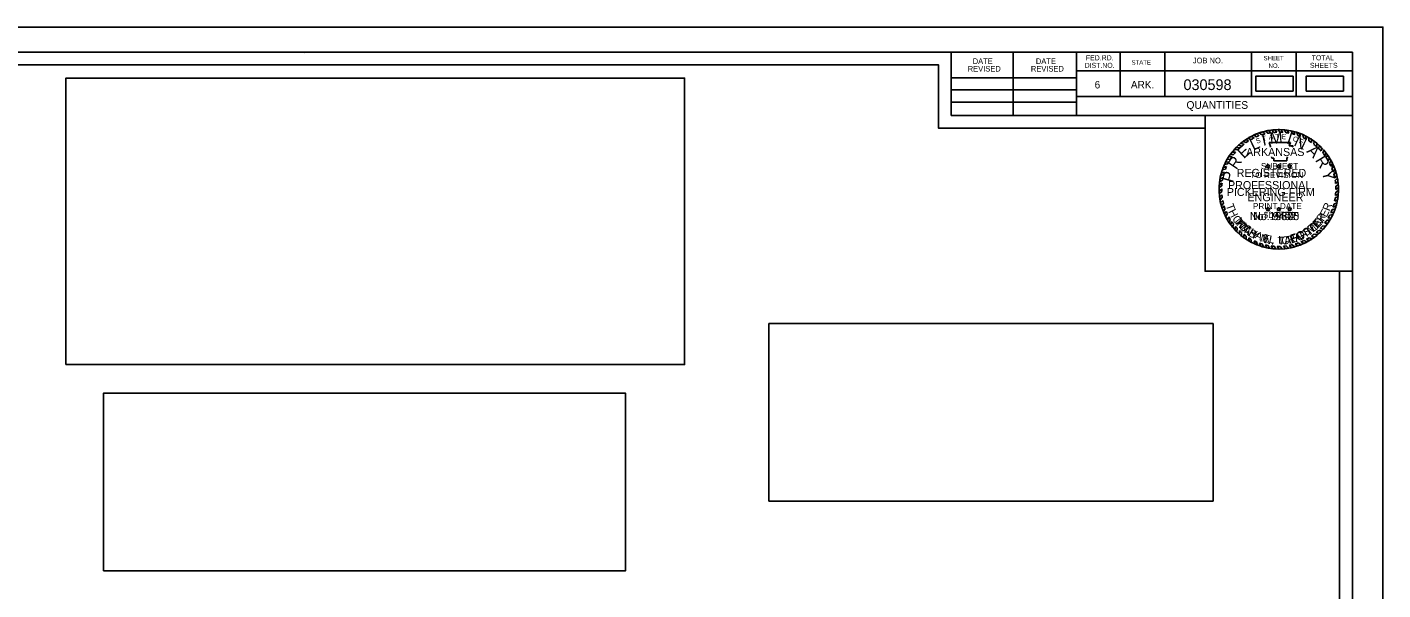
# Model space of a CAD drawing. Extents: x 1369904 to 1372237, y 380119 to 380332.
# Drawn here: x 1370525.1 to 1370736.9, y 380244.5 to 380332.4 of the extents above; entities that cross this region are included whole.
import ezdxf

# ---------------------------------------------------------------- set-up
doc = ezdxf.new("R2010")
doc.units = 0
for name, color, linetype in [('Default', 7, 'Continuous'), ('R_Border', 7, 'Continuous'), ('R_Border Notes', 7, 'Continuous'), ('R_No Plot', 7, 'Continuous'), ('STAMP_PE_CRAFTON', 7, 'Continuous'), ('STAMP_PE_FOSTER', 7, 'Continuous'), ('STAMP_PE_SEAL-INFO', 7, 'Continuous'), ('STAMP_PE_TAEGTMEYER', 7, 'Continuous'), ('STAMP_PE_TXT', 7, 'Continuous'), ('STAMP_PRELIMINARY', 7, 'Continuous')]:
    doc.layers.add(name, color=color, linetype=linetype)

msp = doc.modelspace()

# ---------------------------------------------------------------- linework, layer by layer
at = {"layer": 'Default'}
for points in [[(1370531.17, 380279.71), (1370627.79, 380279.71), (1370627.79, 380324.44), (1370531.17, 380324.44)], [(1370717, 380322.41), (1370722.83, 380322.41), (1370722.83, 380324.72), (1370717, 380324.72)], [(1370724.87, 380322.41), (1370730.7, 380322.41), (1370730.7, 380324.72), (1370724.87, 380324.72)], [(1370640.96, 380258.39), (1370710.35, 380258.39), (1370710.35, 380286.11), (1370640.96, 380286.11)], [(1370537.03, 380247.51), (1370618.58, 380247.51), (1370618.58, 380275.22), (1370537.03, 380275.22)]]:
    msp.add_lwpolyline(points, close=True, dxfattribs=at)
at = {"layer": 'R_Border'}
for p, q in [((1370415.92, 380328.5), (1370732.1, 380328.5)), ((1370568.44, 380328.24), (1370568.44, 380328.24)), ((1370568.44, 380328.24), (1370568.44, 380328.24)), ((1370669.46, 380318.62), (1370669.46, 380328.5)), ((1370679.14, 380318.62), (1370679.14, 380328.5)), ((1370689, 380328.5), (1370689, 380318.62)), ((1370695.84, 380328.5), (1370695.84, 380321.56)), ((1370702.78, 380328.5), (1370702.78, 380321.56)), ((1370716.36, 380328.5), (1370716.36, 380321.56)), ((1370723.3, 380328.5), (1370723.3, 380321.56)), ((1370732.1, 380123.04), (1370732.1, 380328.5)), ((1370669.46, 380324.48), (1370689, 380324.48)), ((1370732.1, 380325.56), (1370689, 380325.56)), ((1370732.1, 380325.58), (1370732.1, 380325.58)), ((1370669.46, 380322.62), (1370689, 380322.62)), ((1370669.46, 380320.68), (1370689, 380320.68)), ((1370732.1, 380321.56), (1370689, 380321.56)), ((1370691.96, 380321.56), (1370732.1, 380321.56)), ((1370732.1, 380318.62), (1370669.46, 380318.62))]:
    msp.add_line(p, q, dxfattribs=at)
at = {"layer": 'R_No Plot'}
for points in [[(1370403.52, 380332.4), (1370736.86, 380332.4), (1370736.86, 380119.06), (1370403.52, 380119.06)], [(1370730.1, 380227.77), (1370417.92, 380227.77), (1370417.92, 380326.5), (1370667.46, 380326.5), (1370667.46, 380316.62), (1370685, 380316.62), (1370709.1, 380316.62), (1370709.1, 380294.29), (1370730.1, 380294.29)], [(1370417.92, 380326.5), (1370667.46, 380326.5), (1370667.46, 380316.62), (1370685, 380316.62), (1370709.1, 380316.62), (1370709.1, 380294.29), (1370730.1, 380294.29), (1370730.1, 380125.04), (1370417.92, 380125.04)], [(1370709.1, 380318.62), (1370732.1, 380318.62), (1370732.1, 380294.29), (1370709.1, 380294.29)]]:
    msp.add_lwpolyline(points, close=True, dxfattribs=at)
at = {"layer": 'STAMP_PE_SEAL-INFO'}
for p, q in [((1370716.71, 380315.54), (1370717.1, 380315.26)), ((1370717.22, 380315.75), (1370717.51, 380315.43)), ((1370717.56, 380315.88), (1370717.94, 380315.57)), ((1370718.16, 380316.06), (1370718.44, 380315.71)), ((1370718.54, 380316.16), (1370718.9, 380315.82)), ((1370719.03, 380316.26), (1370719.32, 380315.89)), ((1370719.54, 380316.33), (1370719.82, 380315.95)), ((1370720.28, 380315.97), (1370719.96, 380316.37)), ((1370720.77, 380315.98), (1370720.5, 380316.39)), ((1370721.23, 380315.96), (1370720.97, 380316.38)), ((1370721.74, 380315.91), (1370721.45, 380316.35)), ((1370722.16, 380315.84), (1370721.91, 380316.3)), ((1370722.73, 380315.72), (1370722.55, 380316.18)), ((1370723.13, 380315.62), (1370722.97, 380316.09)), ((1370723.58, 380315.47), (1370723.44, 380315.95)), ((1370724, 380315.31), (1370723.85, 380315.81)), ((1370724.46, 380315.1), (1370724.36, 380315.6)), ((1370713.97, 380313.61), (1370714.51, 380313.57)), ((1370714.3, 380313.94), (1370714.76, 380313.8)), ((1370714.65, 380314.24), (1370715.17, 380314.14)), ((1370715.02, 380314.56), (1370715.48, 380314.36)), ((1370715.44, 380314.83), (1370715.88, 380314.63)), ((1370715.83, 380315.07), (1370716.26, 380314.85)), ((1370716.28, 380315.33), (1370716.74, 380315.1)), ((1370719.08, 380314.36), (1370722.42, 380314.36)), ((1370719.2, 380314.05), (1370719.08, 380314.36)), ((1370719.3, 380313.75), (1370719.2, 380314.05)), ((1370719.31, 380313.64), (1370719.3, 380313.75)), ((1370722.42, 380314.36), (1370722.2, 380313.87)), ((1370722.2, 380313.87), (1370722.83, 380313.87)), ((1370722.83, 380313.87), (1370722.68, 380313.64)), ((1370724.9, 380314.87), (1370724.82, 380315.38)), ((1370725.29, 380314.65), (1370725.25, 380315.15)), ((1370725.73, 380314.36), (1370725.7, 380314.88)), ((1370726.09, 380314.1), (1370726.12, 380314.58)), ((1370726.53, 380313.72), (1370726.55, 380314.25)), ((1370726.85, 380313.43), (1370726.92, 380313.93)), ((1370727.21, 380313.06), (1370727.27, 380313.58)), ((1370712.31, 380311.32), (1370712.81, 380311.38)), ((1370712.54, 380311.74), (1370713.03, 380311.76)), ((1370712.79, 380312.14), (1370713.3, 380312.18)), ((1370713.02, 380312.49), (1370713.52, 380312.48)), ((1370713.3, 380312.86), (1370713.85, 380312.88)), ((1370713.64, 380313.27), (1370714.17, 380313.23)), ((1370719.5, 380311.93), (1370719.48, 380312.15)), ((1370719.82, 380311.93), (1370719.5, 380311.93)), ((1370719.82, 380311.5), (1370719.82, 380311.93)), ((1370721.85, 380311.5), (1370719.82, 380311.5)), ((1370721.86, 380311.84), (1370721.85, 380311.5)), ((1370721.94, 380312.15), (1370721.86, 380311.84)), ((1370727.48, 380312.74), (1370727.62, 380313.21)), ((1370727.8, 380312.32), (1370727.94, 380312.82)), ((1370728.02, 380312.01), (1370728.2, 380312.47)), ((1370728.33, 380311.51), (1370728.51, 380312)), ((1370728.53, 380311.14), (1370728.76, 380311.59)), ((1370711.52, 380309.18), (1370711.99, 380309.37)), ((1370711.63, 380309.59), (1370712.11, 380309.76)), ((1370711.79, 380310.09), (1370712.27, 380310.23)), ((1370711.94, 380310.5), (1370712.44, 380310.64)), ((1370712.12, 380310.93), (1370712.62, 380311.03)), ((1370728.76, 380310.66), (1370728.99, 380311.15)), ((1370728.9, 380310.32), (1370729.17, 380310.76)), ((1370729.1, 380309.77), (1370729.37, 380310.25)), ((1370729.2, 380309.41), (1370729.5, 380309.86)), ((1370729.34, 380308.85), (1370729.66, 380309.3)), ((1370711.71, 380307.62), (1370711.29, 380307.36)), ((1370711.69, 380307.12), (1370711.29, 380306.79)), ((1370711.74, 380308.04), (1370711.31, 380307.76)), ((1370711.8, 380308.48), (1370711.36, 380308.25)), ((1370711.89, 380308.94), (1370711.42, 380308.69)), ((1370729.41, 380308.47), (1370729.76, 380308.82)), ((1370729.47, 380307.96), (1370729.85, 380308.3)), ((1370729.51, 380307.54), (1370729.9, 380307.84)), ((1370729.52, 380307.03), (1370729.92, 380307.35)), ((1370711.7, 380306.72), (1370711.31, 380306.39)), ((1370711.73, 380306.22), (1370711.36, 380305.86)), ((1370711.78, 380305.79), (1370711.43, 380305.42)), ((1370711.86, 380305.33), (1370711.52, 380304.96)), ((1370729.22, 380304.77), (1370729.69, 380304.98)), ((1370729.33, 380305.23), (1370729.78, 380305.42)), ((1370729.42, 380305.73), (1370729.86, 380305.95)), ((1370729.47, 380306.11), (1370729.9, 380306.37)), ((1370729.51, 380306.62), (1370729.93, 380306.9)), ((1370711.96, 380304.91), (1370711.64, 380304.5)), ((1370712.08, 380304.47), (1370711.78, 380304.05)), ((1370712.22, 380304.04), (1370711.94, 380303.63)), ((1370712.39, 380303.62), (1370712.12, 380303.19)), ((1370712.56, 380303.23), (1370712.33, 380302.77)), ((1370728.56, 380303.05), (1370729.05, 380303.12)), ((1370728.72, 380303.39), (1370729.21, 380303.48)), ((1370728.94, 380303.9), (1370729.42, 380304.03)), ((1370729.07, 380304.28), (1370729.56, 380304.48)), ((1370712.79, 380302.77), (1370712.6, 380302.28)), ((1370713.03, 380302.37), (1370712.84, 380301.9)), ((1370713.23, 380302.06), (1370713.12, 380301.51)), ((1370713.51, 380301.67), (1370713.41, 380301.14)), ((1370713.82, 380301.29), (1370713.73, 380300.77)), ((1370714.12, 380300.95), (1370714.06, 380300.43)), ((1370727.09, 380300.95), (1370727.56, 380300.86)), ((1370727.47, 380301.38), (1370727.93, 380301.3)), ((1370727.78, 380301.78), (1370728.28, 380301.78)), ((1370728.12, 380302.27), (1370728.59, 380302.26)), ((1370728.29, 380302.55), (1370728.79, 380302.61)), ((1370714.44, 380300.63), (1370714.41, 380300.1)), ((1370714.79, 380300.32), (1370714.78, 380299.79)), ((1370715.15, 380300.02), (1370715.16, 380299.5)), ((1370715.48, 380299.77), (1370715.52, 380299.25)), ((1370715.91, 380299.49), (1370715.97, 380298.98)), ((1370716.26, 380299.28), (1370716.35, 380298.77)), ((1370716.74, 380299.03), (1370716.9, 380298.51)), ((1370717.11, 380298.87), (1370717.29, 380298.35)), ((1370717.61, 380298.67), (1370717.82, 380298.17)), ((1370723.65, 380298.69), (1370724.09, 380298.42)), ((1370724.07, 380298.85), (1370724.49, 380298.59)), ((1370724.53, 380299.06), (1370725.01, 380298.85)), ((1370724.94, 380299.28), (1370725.35, 380299.04)), ((1370725.35, 380299.52), (1370725.8, 380299.33)), ((1370725.69, 380299.75), (1370726.13, 380299.56)), ((1370726.16, 380300.09), (1370726.62, 380299.95)), ((1370726.43, 380300.32), (1370726.9, 380300.19)), ((1370726.83, 380300.69), (1370727.27, 380300.55)), ((1370718.02, 380298.54), (1370718.24, 380298.05)), ((1370718.52, 380298.4), (1370718.74, 380297.93)), ((1370718.92, 380298.31), (1370719.17, 380297.86)), ((1370719.42, 380298.23), (1370719.66, 380297.79)), ((1370719.86, 380298.19), (1370720.13, 380297.76)), ((1370720.34, 380298.16), (1370720.65, 380297.74)), ((1370720.8, 380298.16), (1370721.15, 380297.76)), ((1370721.32, 380298.18), (1370721.65, 380297.8)), ((1370721.76, 380298.23), (1370722.13, 380297.87)), ((1370722.21, 380298.3), (1370722.59, 380297.96)), ((1370722.7, 380298.4), (1370723.08, 380298.08)), ((1370723.16, 380298.53), (1370723.57, 380298.23))]:
    msp.add_line(p, q, dxfattribs=at)
for radius, start, end in [(9.32, 111.3124, 114.7026), (9.32, 105.2339, 109.0352), (8.91, 104.0352, 107.3615), (9.32, 99.7525, 102.7765), (8.91, 98.258, 101.0329), (9.32, 93.9381, 96.5517), (8.91, 92.1102, 95.0367), (9.32, 87.7298, 90.6707), (8.91, 85.9628, 88.9097), (9.32, 81.9732, 84.8236), (8.91, 79.9264, 82.696), (9.32, 75.3125, 77.9426), (8.91, 73.5575, 76.2314), (9.32, 69.6061, 72.3058), (9.32, 63.1329, 66.2704), (9.32, 135.4021, 138.3031), (8.91, 133.1331, 136.2562), (9.32, 129.7326, 132.5376), (8.91, 127.5297, 130.9683), (9.32, 123.6199, 126.5906), (8.91, 121.9746, 125.11), (9.32, 117.6544, 120.8099), (8.91, 115.6869, 119.1583), (8.91, 110.3086, 113.1659), (8.91, 67.6248, 70.504), (8.91, 61.1558, 64.3784), (9.32, 56.9003, 60.0942), (8.91, 54.9238, 58.2702), (8.91, 48.3016, 52.0395), (9.32, 50.3492, 53.7159), (8.91, 42.2212, 45.5512), (9.32, 44.3405, 47.3929), (9.32, 152.864, 155.5189), (9.32, 147.0072, 149.899), (8.91, 151.0315, 153.573), (9.32, 141.6056, 144.4486), (8.91, 145.0197, 148.2104), (8.91, 139.301, 142.5873), (8.91, 36.135, 39.5311), (9.32, 38.1247, 41.2316), (8.91, 29.9032, 33.6645), (9.32, 31.9614, 35.4294), (9.32, 25.9391, 29.0125), (9.32, 164.3068, 166.894), (9.32, 158.4077, 161.0701), (8.91, 162.4331, 165.0013), (8.91, 156.3402, 159.2319), (8.91, 23.7732, 27.2211), (8.91, 17.6802, 21.4251), (9.32, 19.9538, 23.3141), (8.91, 11.5444, 15.2364), (9.32, 13.8421, 17.4447), (9.32, 175.7409, 178.2066), (9.32, 170.0003, 172.6878), (8.91, 179.6454, 182.2633), (8.91, 173.73, 176.4734), (8.91, 167.9048, 170.9039), (8.91, 5.7599, 9.0606), (8.91, 359.7329, 3.0639), (9.32, 7.5852, 10.8621), (9.32, 1.7215, 4.7268), (9.32, 181.7251, 184.1626), (9.32, 187.4204, 190.1927), (9.32, 193.0369, 195.9973), (8.91, 185.4539, 188.234), (8.91, 191.2274, 193.9858), (8.91, 348.0778, 351.3435), (8.91, 353.8632, 357.1274), (9.32, 343.8925, 347.035), (9.32, 349.8305, 353.0885), (9.32, 355.7156, 358.9569), (9.32, 198.8967, 201.6281), (8.91, 196.9675, 199.8353), (9.32, 204.5479, 207.4328), (8.91, 202.7761, 205.4791), (8.91, 329.5549, 333.2076), (8.91, 335.6038, 339.1858), (9.32, 331.4037, 334.9332), (8.91, 341.777, 345.0925), (9.32, 337.3837, 340.9933), (9.32, 210.8636, 213.6571), (8.91, 208.7883, 211.7934), (9.32, 216.6115, 219.491), (8.91, 214.1838, 217.2747), (9.32, 222.48, 225.3801), (8.91, 220.3909, 223.3056), (8.91, 316.6531, 320.3711), (9.32, 318.2846, 321.8043), (8.91, 323.5851, 327.4407), (9.32, 325.4405, 328.9872), (9.32, 228.3665, 231.348), (8.91, 226.2494, 229.2407), (8.91, 232.229, 234.9336), (9.32, 234.295, 236.9452), (8.91, 238.2223, 240.8353), (9.32, 240.1977, 242.8613), (8.91, 244.3204, 246.9486), (8.91, 250.3491, 253.1216), (8.91, 286.6423, 289.9783), (8.91, 292.8745, 296.1185), (9.32, 294.6481, 298.2166), (8.91, 299.0768, 302.1724), (9.32, 300.621, 303.8703), (8.91, 304.823, 308.5143), (9.32, 306.3721, 310.208), (8.91, 310.7744, 314.3161), (9.32, 312.4518, 315.6633), (9.32, 246.576, 249.1558), (9.32, 252.5967, 255.3252), (8.91, 256.505, 259.1192), (9.32, 258.4433, 261.1398), (8.91, 262.3783, 265.2012), (9.32, 264.1978, 267.1009), (8.91, 268.3215, 271.277), (9.32, 270.2548, 273.3361), (8.91, 274.6157, 277.4486), (9.32, 276.4239, 279.4357), (8.91, 280.3459, 283.5814), (9.32, 282.3199, 285.3702), (9.32, 288.5709, 291.9733)]:
    msp.add_arc((1370720.6, 380307.07), radius, start, end, dxfattribs=at)
at = {"layer": 'STAMP_PE_TXT'}
for p, q in [((1370718.78, 380310.64), (1370718.59, 380310.78)), ((1370718.59, 380310.78), (1370718.83, 380310.78)), ((1370718.71, 380310.41), (1370718.78, 380310.64)), ((1370718.91, 380310.55), (1370718.71, 380310.41)), ((1370718.83, 380310.78), (1370718.91, 380311.02)), ((1370718.91, 380311.02), (1370718.98, 380310.78)), ((1370719.11, 380310.41), (1370718.91, 380310.55)), ((1370718.98, 380310.78), (1370719.23, 380310.78)), ((1370719.23, 380310.78), (1370719.03, 380310.64)), ((1370719.03, 380310.64), (1370719.11, 380310.41)), ((1370720.48, 380310.64), (1370720.28, 380310.78)), ((1370720.28, 380310.78), (1370720.53, 380310.78)), ((1370720.41, 380310.41), (1370720.48, 380310.64)), ((1370720.6, 380310.55), (1370720.41, 380310.41)), ((1370720.53, 380310.78), (1370720.6, 380311.02)), ((1370720.6, 380311.02), (1370720.68, 380310.78)), ((1370720.8, 380310.41), (1370720.6, 380310.55)), ((1370720.68, 380310.78), (1370720.93, 380310.78)), ((1370720.93, 380310.78), (1370720.73, 380310.64)), ((1370720.73, 380310.64), (1370720.8, 380310.41)), ((1370722.18, 380310.64), (1370721.98, 380310.78)), ((1370721.98, 380310.78), (1370722.23, 380310.78)), ((1370722.1, 380310.41), (1370722.18, 380310.64)), ((1370722.3, 380310.55), (1370722.1, 380310.41)), ((1370722.23, 380310.78), (1370722.3, 380311.02)), ((1370722.3, 380311.02), (1370722.38, 380310.78)), ((1370722.5, 380310.41), (1370722.3, 380310.55)), ((1370722.38, 380310.78), (1370722.62, 380310.78)), ((1370722.62, 380310.78), (1370722.43, 380310.64)), ((1370722.43, 380310.64), (1370722.5, 380310.41)), ((1370718.78, 380303.93), (1370718.59, 380304.08)), ((1370718.59, 380304.08), (1370718.83, 380304.08)), ((1370718.71, 380303.7), (1370718.78, 380303.93)), ((1370718.91, 380303.84), (1370718.71, 380303.7)), ((1370718.83, 380304.08), (1370718.91, 380304.31)), ((1370718.91, 380304.31), (1370718.98, 380304.08)), ((1370719.11, 380303.7), (1370718.91, 380303.84)), ((1370718.98, 380304.08), (1370719.23, 380304.08)), ((1370719.23, 380304.08), (1370719.03, 380303.93)), ((1370719.03, 380303.93), (1370719.11, 380303.7)), ((1370720.48, 380303.93), (1370720.28, 380304.08)), ((1370720.28, 380304.08), (1370720.53, 380304.08)), ((1370720.41, 380303.7), (1370720.48, 380303.93)), ((1370720.6, 380303.84), (1370720.41, 380303.7)), ((1370720.53, 380304.08), (1370720.6, 380304.31)), ((1370720.6, 380304.31), (1370720.68, 380304.08)), ((1370720.8, 380303.7), (1370720.6, 380303.84)), ((1370720.68, 380304.08), (1370720.93, 380304.08)), ((1370720.93, 380304.08), (1370720.73, 380303.93)), ((1370720.73, 380303.93), (1370720.8, 380303.7)), ((1370722.18, 380303.93), (1370721.98, 380304.08)), ((1370721.98, 380304.08), (1370722.23, 380304.08)), ((1370722.1, 380303.7), (1370722.18, 380303.93)), ((1370722.3, 380303.84), (1370722.1, 380303.7)), ((1370722.23, 380304.08), (1370722.3, 380304.31)), ((1370722.3, 380304.31), (1370722.38, 380304.08)), ((1370722.5, 380303.7), (1370722.3, 380303.84)), ((1370722.38, 380304.08), (1370722.62, 380304.08)), ((1370722.62, 380304.08), (1370722.43, 380303.93)), ((1370722.43, 380303.93), (1370722.5, 380303.7))]:
    msp.add_line(p, q, dxfattribs=at)
at = {"layer": 'STAMP_PRELIMINARY'}
msp.add_circle((1370720.6, 380307.07), 9.32, dxfattribs=at)

# ---------------------------------------------------------------- texts
at = {"layer": 'R_Border'}
for s, height, p in [('REVISED', 0.879, (1370672.02, 380325.46)), ('DATE', 0.879, (1370672.8, 380326.64)), ('REVISED', 0.879, (1370681.88, 380325.46)), ('DATE', 0.879, (1370682.66, 380326.64)), ('DIST.NO.', 0.782, (1370690.28, 380326.04)), ('FED.RD.', 0.782, (1370690.48, 380327.22)), ('STATE', 0.684, (1370697.6, 380326.54)), ('JOB NO.', 0.879, (1370707.18, 380326.74)), ('SHEET', 0.684, (1370718.22, 380327.22)), ('NO.', 0.684, (1370719, 380326.04)), ('SHEETS', 0.782, (1370725.46, 380326.04)), ('TOTAL', 0.782, (1370725.74, 380327.22)), ('6', 1.17, (1370691.84, 380322.82)), ('ARK.', 1.172, (1370697.5, 380322.82))]:
    msp.add_text(s, height=height, dxfattribs=at).set_placement(p)
at = {"layer": 'R_Border Notes'}
for s, height, p in [('030598', 1.68, (1370705.72, 380322.57)), ('QUANTITIES', 1.2, (1370706.18, 380319.64))]:
    msp.add_text(s, height=height, dxfattribs=at).set_placement(p)
at = {"layer": 'STAMP_PE_CRAFTON'}
msp.add_text('No. 12370', height=1.25, dxfattribs=at).set_placement((1370716.07, 380302.26))
for s, rotation, p in [('T', 310.7442, (1370713.57, 380301.97)), ('O', 317.6422, (1370714.24, 380301.15)), ('N', 324.4537, (1370715.08, 380300.37)), ('Y', 331.1686, (1370716.12, 380299.65)), ('F', 28.7821, (1370724.27, 380299.2)), ('T', 34.1136, (1370725.18, 380299.71)), ('O', 41.8391, (1370726.04, 380300.31)), ('N', 49.2411, (1370726.89, 380301.09)), ('N', 347.4752, (1370718.17, 380298.74)), ('.', 356.8926, (1370719.4, 380298.46)), ('C', 6.0117, (1370721.08, 380298.41)), ('R', 14.8189, (1370722.17, 380298.52)), ('A', 20.5125, (1370723.29, 380298.82))]:
    msp.add_text(s, height=1.25, rotation=rotation, dxfattribs=at).set_placement(p)
at = {"layer": 'STAMP_PE_FOSTER'}
msp.add_text('No. 9402', height=1.25, dxfattribs=at).set_placement((1370716.59, 380302.26))
for s, rotation, p in [('R', 54.5031, (1370727.33, 380301.88)), ('M', 308.339, (1370713.72, 380302.09)), ('I', 314.1842, (1370714.52, 380301.15)), ('C', 319.8733, (1370714.87, 380300.8)), ('H', 327.7235, (1370715.8, 380300.06)), ('S', 31.7234, (1370724.8, 380299.68)), ('T', 39.4194, (1370725.75, 380300.31)), ('E', 46.9613, (1370726.61, 380301.06)), ('A', 335.7276, (1370716.78, 380299.48)), ('E', 343.5779, (1370717.92, 380299.01)), ('L', 350.8115, (1370718.98, 380298.73)), ('L', 1.2666, (1370720.52, 380298.58)), ('.', 6.8035, (1370721.56, 380298.63)), ('F', 15.8691, (1370722.64, 380298.82)), ('O', 23.719, (1370723.68, 380299.15))]:
    msp.add_text(s, height=1.2, rotation=rotation, dxfattribs=at).set_placement(p)
at = {"layer": 'STAMP_PE_TAEGTMEYER'}
for s, rotation, p in [('T', 289.646, (1370712.3, 380304.58)), ('R', 69.57, (1370728.55, 380303.58)), ('H', 296.7339, (1370712.66, 380303.59)), ('O', 303.7708, (1370713.25, 380302.49)), ('Y', 53.9986, (1370727.38, 380301.66)), ('E', 63.0984, (1370728.05, 380302.6)), ('M', 314.2033, (1370713.91, 380301.53)), ('A', 321.0594, (1370714.87, 380300.57)), ('S', 327.8239, (1370715.69, 380299.93)), ('T', 31.466, (1370724.7, 380299.42)), ('M', 39.3, (1370725.6, 380299.97)), ('E', 46.8094, (1370726.64, 380300.84)), ('N', 344.2727, (1370717.59, 380298.92)), ('.', 350.6464, (1370718.8, 380298.59)), ('T', 3.0061, (1370720.47, 380298.39)), ('A', 8.9826, (1370721.52, 380298.44)), ('E', 17.6836, (1370722.55, 380298.6)), ('G', 23.3052, (1370723.6, 380298.93))]:
    msp.add_text(s, height=1.25, rotation=rotation, dxfattribs=at).set_placement(p)
msp.add_text('No. 19605', height=1.25, dxfattribs=at).set_placement((1370716.07, 380302.26))
at = {"layer": 'STAMP_PE_TXT'}
for s, rotation, p in [('A', 9.0679, (1370719.09, 380314.8)), ('T', 1.8248, (1370720.08, 380314.93)), ('E', 355.2002, (1370720.99, 380314.93)), ('S', 23.5541, (1370717.2, 380314.17)), ('T', 16.311, (1370718.13, 380314.54)), ('O', 342.2506, (1370722.71, 380314.66)), ('F', 335.0075, (1370723.68, 380314.32))]:
    msp.add_text(s, height=0.781, rotation=rotation, dxfattribs=at).set_placement(p)
for s, p in [('ARKANSAS', (1370715.5, 380312.28)), ('REGISTERED', (1370714.02, 380309.01)), ('PROFESSIONAL', (1370712.67, 380307.11)), ('ENGINEER', (1370715.71, 380305.21))]:
    msp.add_text(s, height=1.25, dxfattribs=at).set_placement(p)
at = {"layer": 'STAMP_PRELIMINARY'}
for s, rotation, p in [('I', 12.5248, (1370718.14, 380313.85)), ('M', 3.1074, (1370719.24, 380314.16)), ('I', 342.3164, (1370721.71, 380314.23)), ('E', 42.3578, (1370715.13, 380311.76)), ('L', 25.513, (1370716.61, 380313.09)), ('N', 333.9382, (1370722.82, 380313.96)), ('A', 315.6579, (1370724.85, 380312.93)), ('R', 56.2292, (1370713.98, 380310.03)), ('R', 301.3831, (1370726.22, 380311.62)), ('P', 73.913, (1370713.43, 380308.01)), ('Y', 283.2593, (1370727.31, 380309.83))]:
    msp.add_text(s, height=1.8, rotation=rotation, dxfattribs=at).set_placement(p)
for s, height, p in [('TO REVISION', 0.96, (1370716.14, 380308.83)), ('SUBJECT', 0.96, (1370717.8, 380310.22)), ('PICKERING FIRM', 1.25, (1370712.48, 380306.03)), ('PRINT DATE', 0.96, (1370716.56, 380303.98)), ('$DATE$', 0.96, (1370718.24, 380302.6))]:
    msp.add_text(s, height=height, dxfattribs=at).set_placement(p)

doc.saveas('drawing.dxf')
